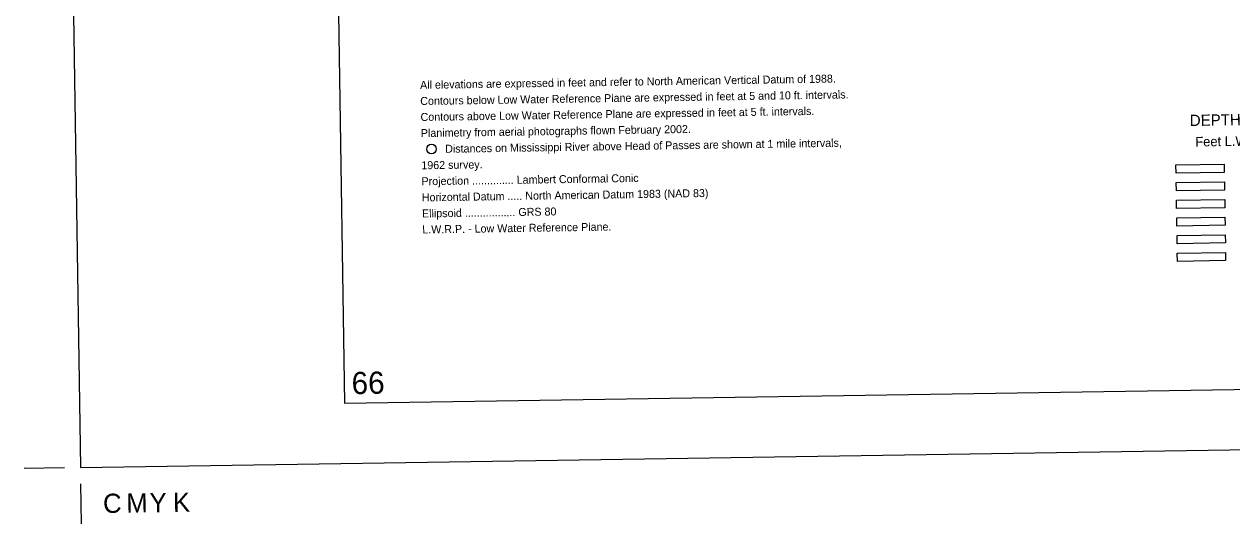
# Model space of a CAD drawing. Extents: x 3823584 to 3861785, y 301729 to 327625.
# Drawn here: x 3823956 to 3836481, y 301729 to 306914 of the extents above; entities that cross this region are included whole.
import ezdxf

# ---------------------------------------------------------------- set-up
doc = ezdxf.new("R2010")
doc.units = 0
for name, color, linetype in [('G-ANNO-NPLT', 7, 'Continuous'), ('V-ANNO-DIMS', 7, 'Continuous'), ('V-ANNO-NOTE', 7, 'Continuous'), ('V-ANNO-SYMB', 7, 'Continuous'), ('V-ANNO-TEXT', 7, 'Continuous'), ('V-TOPO-DPTH', 7, 'Continuous')]:
    doc.layers.add(name, color=color, linetype=linetype)

msp = doc.modelspace()

# ---------------------------------------------------------------- linework, layer by layer
at = {"layer": 'G-ANNO-NPLT'}
msp.add_lwpolyline([(3824539, 302313), (3861202, 302878), (3860829, 327042), (3824167, 326476)], close=True, dxfattribs=at)
at = {"layer": 'V-ANNO-DIMS'}
for p, q in [((3824373, 302310), (3823956, 302304)), ((3824542, 302146), (3824548, 301729))]:
    msp.add_line(p, q, dxfattribs=at)
at = {"layer": 'V-ANNO-NOTE'}
msp.add_circle((3828181, 305618), 50, dxfattribs=at)
at = {"layer": 'V-ANNO-SYMB'}
msp.add_lwpolyline([(3827280, 302980), (3860359, 303490), (3860006, 326404), (3826926, 325894), (3827280, 302980)], dxfattribs=at)
at = {"layer": 'V-TOPO-DPTH'}
for points in [[(3835902, 305453), (3836402, 305461), (3836403, 305376), (3835903, 305368)], [(3835905, 305270), (3836405, 305278), (3836406, 305193), (3835906, 305185)], [(3835907, 305087), (3836407, 305095), (3836409, 305010), (3835909, 305002)], [(3835910, 304904), (3836410, 304912), (3836412, 304827), (3835912, 304819)], [(3835913, 304721), (3836413, 304729), (3836414, 304644), (3835914, 304636)], [(3835916, 304538), (3836416, 304546), (3836417, 304461), (3835917, 304453)]]:
    msp.add_lwpolyline(points, close=True, dxfattribs=at)

# ---------------------------------------------------------------- texts
at = {"layer": 'V-ANNO-DIMS'}
for s, p in [('C', (3824776, 301842)), ('M', (3825017, 301845)), ('Y', (3825259, 301849)), ('K', (3825501, 301853))]:
    msp.add_text(s, height=199, rotation=0.8834, dxfattribs=at).set_placement(p)
at = {"layer": 'V-ANNO-NOTE'}
for s, rotation, p in [('All elevations are expressed in feet and refer to North American Vertical Datum of 1988.', 0.8834, (3828063, 306242)), ('Contours below Low Water Reference Plane are expressed in feet at 5 and 10 ft. intervals.', 0.8834, (3828065, 306075)), ('Contours above Low Water Reference Plane are expressed in feet at 5 ft. intervals.', 0.8834, (3828068, 305909)), ('Planimetry from aerial photographs flown February 2002.', 0.8834, (3828071, 305742)), ('Distances on Mississippi River above Head of Passes are shown at 1 mile intervals,', 0.8834, (3828323, 305579)), ('1962 survey.', 0.8834, (3828076, 305408)), ('Projection .............. Lambert Conformal Conic', 0.8833, (3828078, 305242)), ('Horizontal Datum ..... North American Datum 1983 (NAD 83)', 0.8833, (3828081, 305075)), ('Ellipsoid ................. GRS 80', 0.8833, (3828083, 304908)), ('L.W.R.P. - Low Water Reference Plane.', 0.8833, (3828086, 304742))]:
    msp.add_text(s, height=83, rotation=rotation, dxfattribs=at).set_placement(p)
at = {"layer": 'V-ANNO-TEXT'}
msp.add_text('66', height=230, rotation=0.8834, dxfattribs=at).set_placement((3827354, 303075))
at = {"layer": 'V-TOPO-DPTH'}
for s, height, p in [('DEPTH AREAS', 116.7, (3836046, 305857)), ('Feet L.W.R.P.', 100, (3836103, 305644))]:
    msp.add_text(s, height=height, rotation=0.8834, dxfattribs=at).set_placement(p)

doc.saveas('drawing.dxf')
